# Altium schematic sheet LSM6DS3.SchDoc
size A
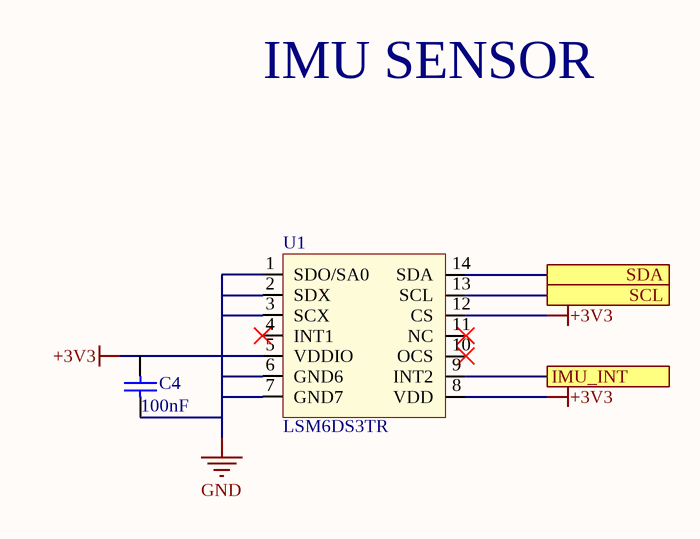
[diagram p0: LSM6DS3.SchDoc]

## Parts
C4  value 100nF  [CAP-0402]  (hidden comment: C0402C104K3PACTU)
U1  LSM6DS3TR  [VFLGA14]

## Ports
IMU_INT, SCL, SDA

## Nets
+3V3: C4.2 U1.5(VDDIO) U1.8(VDD) U1.12(CS)
GND: C4.1 U1.1(SDO/SA0) U1.2(SDX) U1.3(SCX) U1.6(GND6) U1.7(GND7)
IMU_INT: U1.9(INT2) ; port IMU_INT
SCL: U1.13(SCL) ; port SCL
SDA: U1.14(SDA) ; port SDA

Not connected (* = marked no-connect by the designer): U1 4(INT1)* 10(OCS)* 11(NC)*

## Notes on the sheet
- IMU SENSOR

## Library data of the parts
C4 = C0014-A.3: CAP CHIP 0402 100nF 25V X5R 10%; Manufacturer: KEMET; Code Arduino: 0132
U1 = U0010-A.3: IMU ACCEL/GYRO I2C/SPI 14VFLGA; Manufacturer: STMicroelectronics; Max Supply Voltage: 3.6V; Output Type: SPI,I2C,Digital; Min Supply Voltage: 1.71V; Sensor Type: Accelerometer,Gyroscope,3 Axis; Code Arduino: 2326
